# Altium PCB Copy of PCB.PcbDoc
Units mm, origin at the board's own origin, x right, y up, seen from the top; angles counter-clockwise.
Board outline 40 x 38 mm, 2 copper layers (Top Layer, Bottom Layer); 39 components, 67 nets, 273 pads, 70 vias.
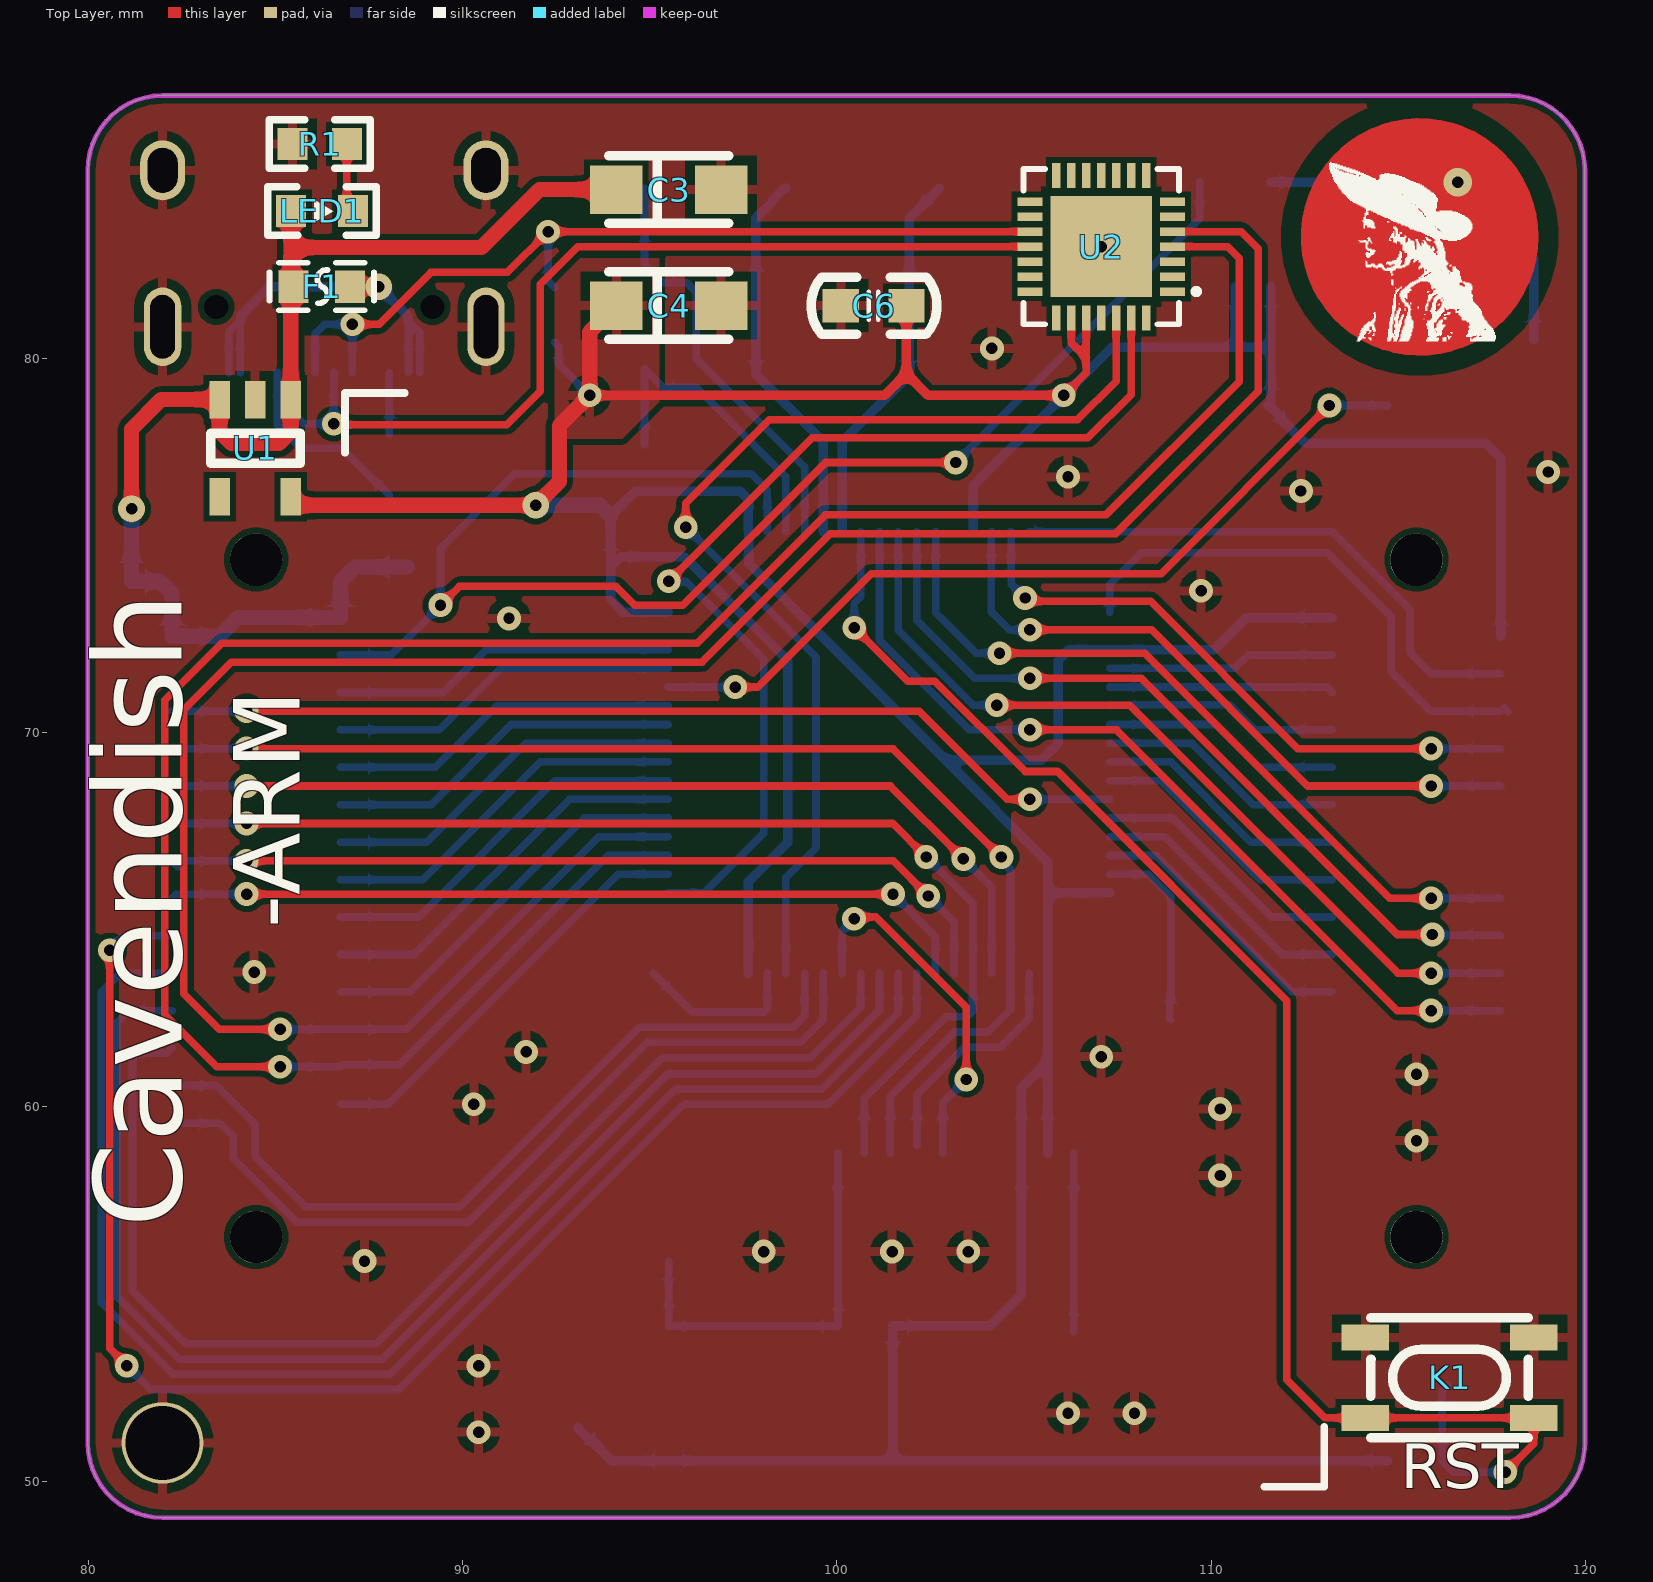
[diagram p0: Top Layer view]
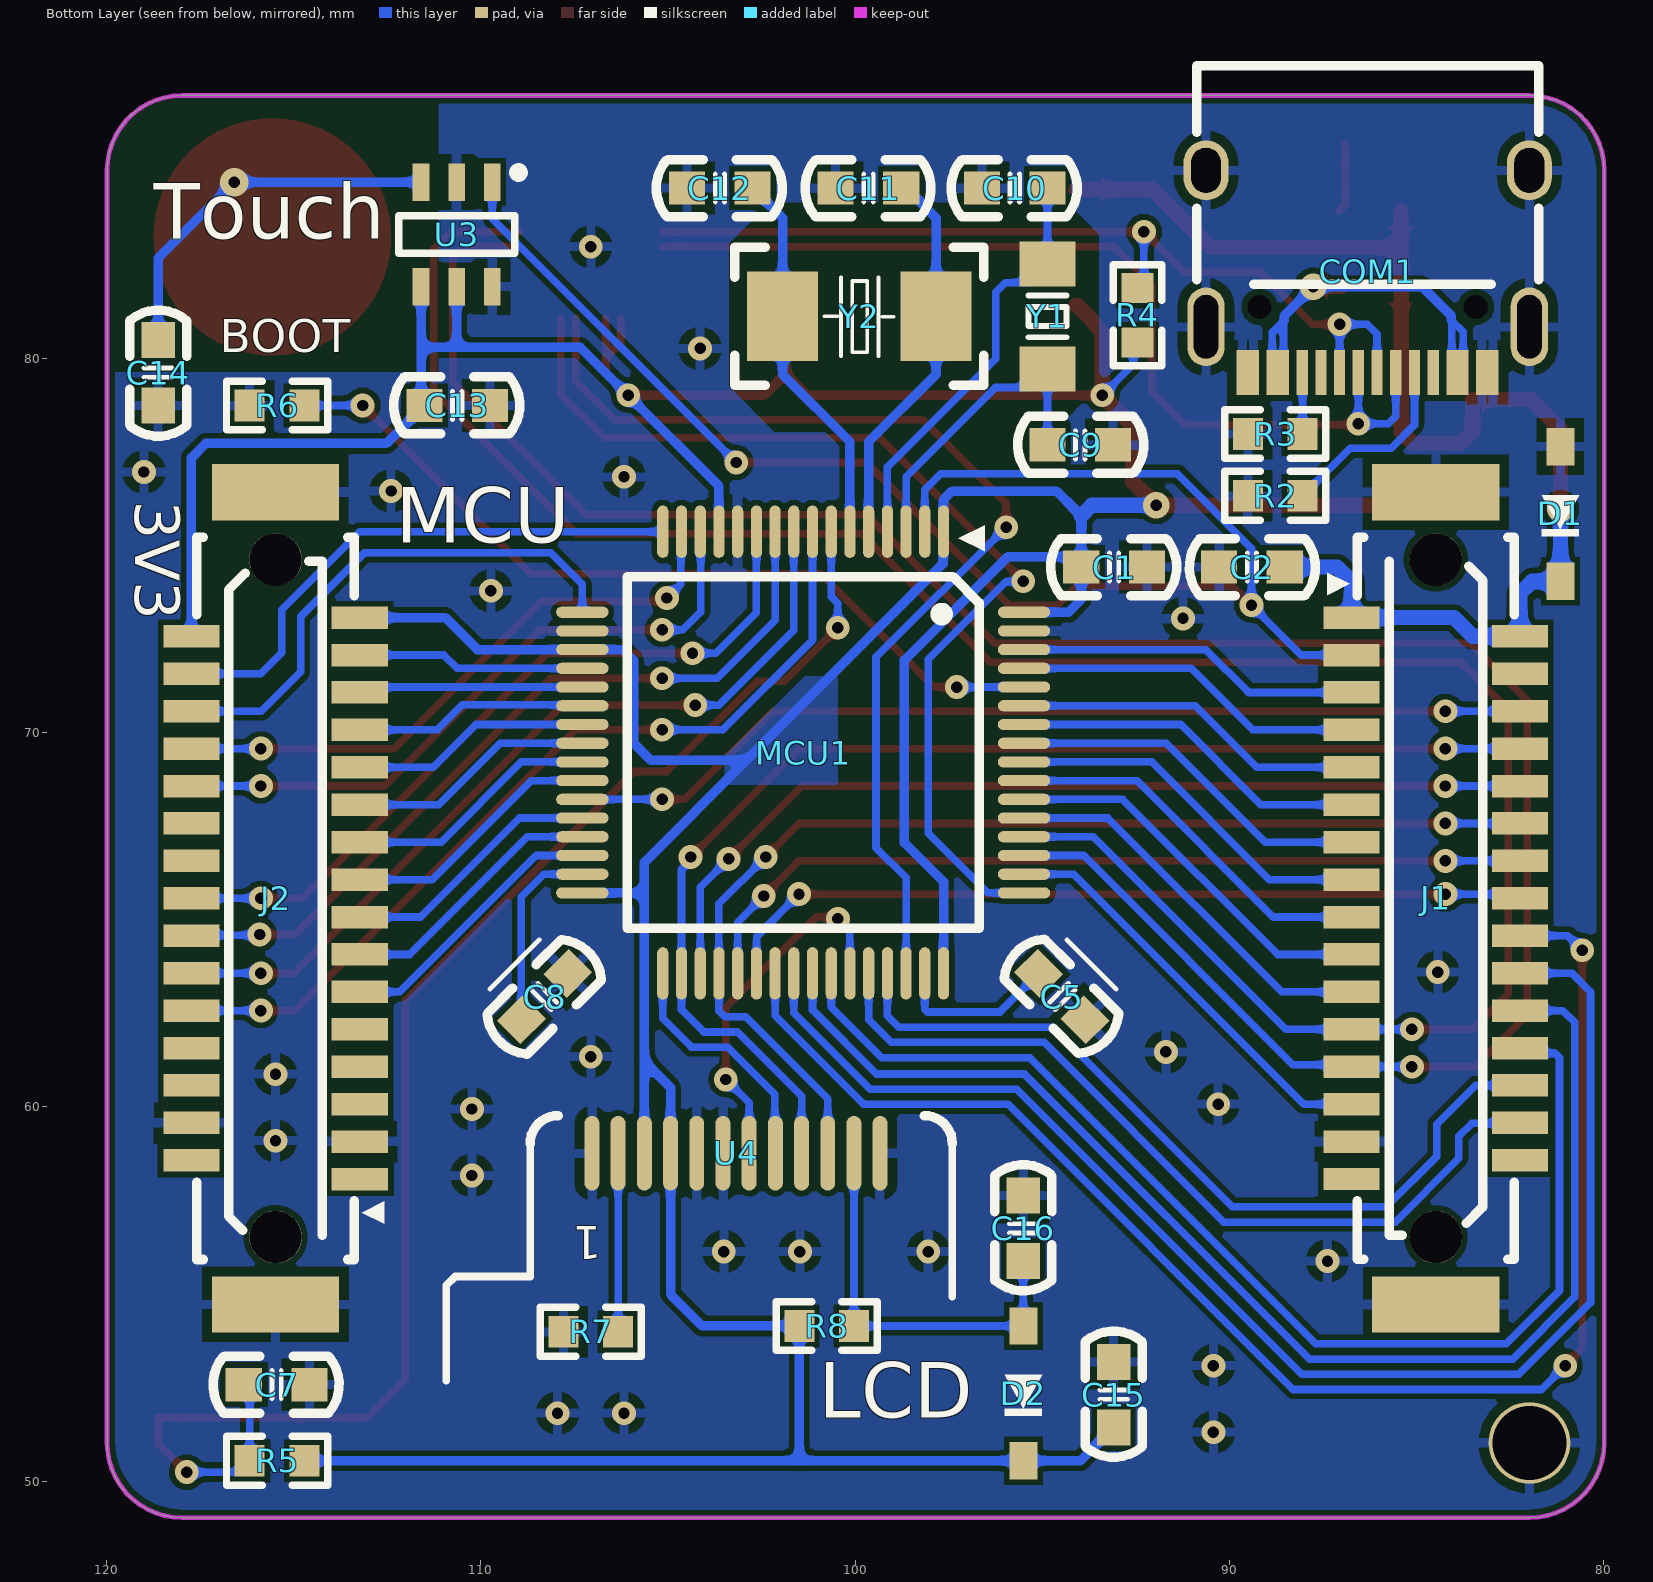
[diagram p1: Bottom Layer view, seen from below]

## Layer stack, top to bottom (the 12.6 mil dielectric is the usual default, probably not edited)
Top Solder: solder mask 0.0102, Solder Resist, Dk 3.5
Top Layer: signal copper 0.0356
Dielectric 1: dielectric 0.32, FR-4, Dk 4.8
Bottom Layer: signal copper 0.0356
Bottom Solder: solder mask 0.0102, Solder Resist, Dk 3.5

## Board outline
79.983,51.022 ccw(c81.983,51.022) 81.983,49.022 117.983,49.022 ccw(c117.983,51.022) 119.983,51.022 119.983,85.022 ccw(c117.983,85.022) 117.983,87.022 82.808,87.022 81.983,87.022 ccw(c81.983,85.022) 79.983,85.022

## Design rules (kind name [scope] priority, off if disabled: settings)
Clearance [All] p1: gap=0.152 ignorepadtopadclearanceinfootprint=TRUE
HoleSize [All] p1: absolutevalues=TRUE maxlimit=10.16 minlimit=0.025 maxpercent=80.000 minpercent=20.000
HoleToHoleClearance [All] p1: gap=0.152 allowstackedmicrovias=TRUE
MinimumSolderMaskSliver [All] p1: minsoldermaskwidth=0.025
PolygonConnect [All] p1: connectstyle=Relief reliefconductorwidth=0.254 reliefentries=4 polygonreliefangle="90 Angle" airgapwidth=0.254
RoutingVias [All] p1: holewidth=0.711 width=1.27 viastyle="Through Hole" minholewidth=0.305 minwidth=0.406 maxholewidth=0.711 maxwidth=1.27
SilkToSilkClearance [All] p1: silktosilkclearance=0
SilkToSolderMaskClearance [IsPad] p1: minsilkscreentomaskgap=0 clearancetoexposedcopper=TRUE
SolderMaskExpansion [All] p1: expansion=0.102 istentingtop=FALSE
Width [All] p1: maxlimit=1.27 minlimit=0.203 preferedwidth=0.254
25 further rules are at their usual default settings.

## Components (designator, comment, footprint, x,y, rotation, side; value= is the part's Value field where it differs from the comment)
C1 "100NF" CAP_0603 92.202,74.422 r0 bottom
C2 "100NF" CAP_0603 90.272,74.422 r180 bottom
C3 "100UF" CAP_3216_A 95.504,84.506 r180 top
C4 "100UF" CAP_3216_A 95.504,81.407 r180 top
C5 "10UF" CAP_0603 93.857,62.327 r45 bottom
C6 "100NF" CAP_0603 100.101,81.407 r0 top
C7 "100NF" CAP_0603 114.579,52.578 r0 bottom
C8 "10UF" CAP_0603 107.676,63.566 r315 bottom
C9 "10PF" CAP_0603 94.859,77.688 r180 bottom
C10 "10PF" CAP_0603 94.859,84.547 r0 bottom
C11 "22PF" CAP_0603 98.765,84.547 r0 bottom
C12 "22PF" CAP_0603 102.737,84.547 r0 bottom
C13 "100NF" CAP_0603 109.753,78.74 r0 bottom
C14 "22PF" CAP_0603 118.618,80.493 r270 bottom
C15 "100NF" CAP_0603 93.091,51.435 r90 bottom
C16 "4.7UF" CAP_0603 95.504,55.88 r90 bottom
COM1 "Type-C" USB-Type-C_16A 86.303,84.997 r0 bottom
D1 "B5819W" DIODE_SOD123 81.153,77.641 r270 bottom
D2 "1N4148" DIODE_SOD123 95.504,54.146 r270 bottom
F1 "FUSE" Fuse_0603 86.233,81.915 r0 top
J1 "31PIN" BTB-DM3-31P 84.483,74.622 r270 bottom
J2 "31PIN" BTB-DM3-31P 115.483,56.522 r90 bottom
K1 "KEY" KEY_SMD 114.118,53.839 r0 top
LED1 "LED_R/G/B/Y" LED_0603_R 86.241,83.932 r180 top
MCU1 "STM32F405RET6" LQFP_64_10X10 101.386,69.466 r0 bottom
R1 "10K" RESC_0603_2 86.182,85.725 r0 top
R2 "5.1K" RESC_0603_2 88.773,76.327 r180 bottom
R3 "5.1K" RESC_0603_2 88.773,77.978 r180 bottom
R4 "5.1K" RESC_0603_2 92.456,81.153 r90 bottom
R5 "10K" RESC_0603_2 115.443,50.546 r0 bottom
R6 "10K" RESC_0603_2 115.443,78.74 r0 bottom
R7 "20R" RESC_0603_2 107.059,53.991 r180 bottom
R8 "4.7K" RESC_0603_2 100.759,54.146 r180 bottom
U1 "SPX3819M5-L" SOT23_5 84.455,77.597 r90 top
U2 "CH549F" QFN28-4X4L 108.969,81.783 r180 top
U3 "TTP223" SOT-23-6 109.692,84.709 r270 bottom
U4 "TFT_1.3_12Pin" LCD_1.3B 107.537,59.26 r180 top
Y1 "32KHz" XTAL_SMD_3215 94.859,81.118 r270 bottom
Y2 "8MHz" XTAL-SMD5032-2P 99.886,81.124 r180 bottom

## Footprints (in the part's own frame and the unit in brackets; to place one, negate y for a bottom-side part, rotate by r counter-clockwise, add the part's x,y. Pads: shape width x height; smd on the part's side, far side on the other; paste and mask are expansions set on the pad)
BTB-DM3-31P [mm]
  rect 0.6x1.5 smd: 1(1.55,-2.25) 2(2.05,2.25) 3(2.55,-2.25) 4(3.05,2.25) 5(3.55,-2.25) 6(4.05,2.25) 7(4.55,-2.25) 8(5.05,2.25) 9(5.55,-2.25) 10(6.05,2.25) 11(6.55,-2.25) 12(7.05,2.25) 13(7.55,-2.25) 14(8.05,2.25) 15(8.55,-2.25) 16(9.05,2.25) 17(9.55,-2.25) 18(10.05,2.25) 19(10.55,-2.25) 20(11.05,2.25) 21(11.55,-2.25) 22(12.05,2.25) 23(12.55,-2.25) 24(13.05,2.25) 25(13.55,-2.25) 26(14.05,2.25) 27(14.55,-2.25) 28(15.05,2.25) 29(15.55,-2.25) 30(16.05,2.25) 31(16.55,-2.25)
  rect 1.5x3.4 smd: 32(19.9,0) 33(-1.8,0)
  round 1.4 hole 1.4 unplated: ""(0,0) ""(18.1,0)
  silkscreen extent -0.6,-2.9 18.7,2.1, body extent -1.51,-2.81 19.59,2.79, height 3.35
CAP_0603 [mil]
  rect 38x35 smd: 1(0,0) 2(69,0)
  silkscreen extent -31,-30 101,30, body extent 4,-16 67,16, height 12
CAP_3216_A [mm]
  rect 1.4x1.3 smd: 1(1.4,0) 2(-1.4,0)
  silkscreen extent -1.6,-0.9 1.6,0.9, body extent -1.6,-0.8 1.6,0.8, height 1.6
DIODE_SOD123 [mm]
  rect 1x0.75 smd: 1(0,0) 2(3.6,0)
  silkscreen extent 1.3,-0.5 2.4,0.5, body extent -0.05,-0.8 3.65,0.8, height 1.27
Fuse_0603 [mil]
  rect 31.8x34 smd mask+2: 1(-29.7,0) 2(29.7,0)
  silkscreen extent -55,-25 55,25, body extent -33,-18 34,18, height 30
KEY_SMD [mm] "3*4*2.5MM"
  rect 1.27x0.7 smd: 1(0,0) 1(4.5,0) 2(0,-2.15) 2(4.5,-2.15)
  silkscreen extent 0.15,-2.68 4.35,0.52, body extent -0.1,-2.67 4.6,0.53, height 2.51
LCD_1.3B [mm]
  oval 0.4x2 smd far side: 1(0.508,0.5) 2(1.208,0.5) 3(1.908,0.5) 4(2.608,0.5) 5(3.308,0.5) 6(4.008,0.5) 7(4.708,0.5) 8(5.408,0.5) 9(6.108,0.5) 10(6.808,0.5) 11(7.508,0.5) 12(8.208,0.5)
  silkscreen extent -5.48,-19.81 20.68,9.41, body extent -5.48,-19.81 20.68,9.41, height 1
LED_0603_R [mm]
  rect 0.8x0.85 smd: 1(-0.832,0) 2(0.832,0)
  silkscreen extent -1.45,-0.65 1.45,0.65, body extent -0.81,-0.4 0.81,0.4, height 0.6
LQFP_64_10X10 [mm]
  oval 0.3x1.4 smd: 1(-3.75,-5.9) 2(-3.25,-5.9) 3(-2.75,-5.9) 4(-2.25,-5.9) 5(-1.75,-5.9) 6(-1.25,-5.9) 7(-0.75,-5.9) 8(-0.25,-5.9) 9(0.25,-5.9) 10(0.75,-5.9) 11(1.25,-5.9) 12(1.75,-5.9) 13(2.25,-5.9) 14(2.75,-5.9) 15(3.25,-5.9) 16(3.75,-5.9) 33(3.75,5.9) 34(3.25,5.9) 35(2.75,5.9) 36(2.25,5.9) 37(1.75,5.9) 38(1.25,5.9) 39(0.75,5.9) 40(0.25,5.9) 41(-0.25,5.9) 42(-0.75,5.9) 43(-1.25,5.9) 44(-1.75,5.9) 45(-2.25,5.9) 46(-2.75,5.9) 47(-3.25,5.9) 48(-3.75,5.9)
  oval 1.4x0.3 smd: 17(5.9,-3.75) 18(5.9,-3.25) 19(5.9,-2.75) 20(5.9,-2.25) 21(5.9,-1.75) 22(5.9,-1.25) 23(5.9,-0.75) 24(5.9,-0.25) 25(5.9,0.25) 26(5.9,0.75) 27(5.9,1.25) 28(5.9,1.75) 29(5.9,2.25) 30(5.9,2.75) 31(5.9,3.25) 32(5.9,3.75) 49(-5.9,3.75) 50(-5.9,3.25) 51(-5.9,2.75) 52(-5.9,2.25) 53(-5.9,1.75) 54(-5.9,1.25) 55(-5.9,0.75) 56(-5.9,0.25) 57(-5.9,-0.25) 58(-5.9,-0.75) 59(-5.9,-1.25) 60(-5.9,-1.75) 61(-5.9,-2.25) 62(-5.9,-2.75) 63(-5.9,-3.25) 64(-5.9,-3.75)
  silkscreen extent -4.85,-6.08 4.7,4.7, body extent -6.07,-6.07 6.07,6.07, height 1.62
QFN28-4X4L [mil]
  rect 26.2x8.8 smd mask+2: 1(0,0) 2(0,-15.7) 3(0,-31.5) 4(0,-47.2) 5(0,-63) 6(0,-78.7) 7(0,-94.4) 15(150.2,-94.4) 16(150.2,-78.7) 17(150.2,-63) 18(150.2,-47.2) 19(150.2,-31.5) 20(150.2,-15.7) 21(150.2,0)
  rect 8.8x26.2 smd mask+2: 8(27.9,-122.3) 9(43.6,-122.3) 10(59.4,-122.3) 11(75.1,-122.3) 12(90.9,-122.3) 13(106.6,-122.3) 14(122.3,-122.3) 22(122.3,27.9) 23(106.6,27.9) 24(90.9,27.9) 25(75.1,27.9) 26(59.4,27.9) 27(43.6,27.9) 28(27.9,27.9)
  rect 106.3x106.3 smd mask+2: 29(75.1,-47.2)
  silkscreen extent -28,-129 157,35, body extent -4,-126 154,32, height 35
RESC_0603_2 [mm]
  rect 0.8x0.85 smd: 1(-0.73,0) 2(0.73,0)
  silkscreen extent -1.35,-0.65 1.35,0.65, body extent -0.8,-0.4 0.8,0.4, height 0.38
SOT23_5 [mm]
  rect 1x0.55 smd: 1(1.3,-0.95) 2(1.3,0) 3(1.3,0.95) 4(-1.3,0.95) 5(-1.3,-0.95)
  silkscreen extent -0.4,-1.21 0.4,1.19, body extent -1.52,-1.51 1.48,1.49, height 1.3
SOT-23-6 [mm]
  rect 1x0.45 smd: 1(0,0) 2(0,-0.95) 3(0,-1.9) 4(2.794,-1.9) 5(2.794,-0.95) 6(2.794,0)
  silkscreen extent -0.38,-2.5 1.91,0.82, body extent -0.01,-2.45 2.8,0.55, height 1.15
USB-Type-C_16A [mm]
  round 0 hole 0.65: 0(-2.89,3.625) 0(2.89,3.625)
  oval 1.2x1.6 hole 0.8 slot 1.2 at 90 deg: 1(-4.32,-0.025) 1(4.32,-0.025)
  oval 1x2.1 hole 0.66 slot 1.7 at 90 deg: 1(-4.32,4.155) 1(4.32,4.155)
  rect 0.3x1.2 smd: A1(-3.35,5.375) A4(-2.55,5.375) A5(-1.25,5.375) A6(-0.25,5.375) A7(0.25,5.375) A8(-1.75,5.375) A9(2.55,5.375) A12(3.35,5.375) B1(3.05,5.375) B4(2.25,5.375) B5(1.75,5.375) B6(0.75,5.375) B7(-0.75,5.375) B8(1.25,5.375) B9(-2.25,5.375) B12(-3.05,5.375)
  silkscreen extent -4.57,-2.82 4.57,3.02, body extent -4.47,-2.63 4.47,5.27, height 3.25
XTAL-SMD5032-2P [mil]
  rect 74.8x94.5 smd mask+2: 1(-80.7,0) 2(80.7,0)
  silkscreen extent -131,-73 131,73, body extent -98,-63 99,63, height 39
XTAL_SMD_3215 [mm]
  rect 1.2x1.5 smd: 1(-1.4,0) 2(1.4,0)
  silkscreen extent -0.56,-0.51 0.56,0.51, body extent -1.61,-0.76 1.61,0.76, height 0.91

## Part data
C1 C2 C5 C6 C7 C8 C9 C10 C11 C12 C13 C14 C15 C16: library part CAP, "CAP  12~50V"
C3 C4: library part CAP_TA, "CAP  6~12V  钽电容"
COM1: library part USB-type_c, "USB"
D1 D2: library part Diode-SM, "Diode_肖特基/二极管"
J1 J2: library part BTB_DF3_31Pin, "BTB"
K1: "Key"
LED1: library part LED_SMT, "LED"
MCU1: library part STM32f4_R, "MCU"
R1 R5 R6 R7 R8: library part RES_S, "RES 贴片"
R2 R3 R4: library part RES, "RES 贴片"
U1: "DC-DC   3.3V  500ma"
U2: "MCU", External Clock Frequency Rang=6MHz~25MHz, JLCPCB Part Class="Extended Part", Manufacturer=WCH(南京沁恒), Maximum Frequency=48MHz, Operating Temperature Range=-40~+70, Supply Voltage Range=3.3V~5V
U3: "触摸芯片"
U4: library part "LCD_1.3   T", "ST7789V-SPI"
Y1 Y2: library part XTAL, "CRYSTAL"

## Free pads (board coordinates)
  round 2.184 hole 1.981: 0(81.983,51.022)

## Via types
v1: diameter 0.635, hole 0.305, Top Layer to Bottom Layer, tented both sides, 66 vias
v2: diameter 0.711, hole 0.305, Top Layer to Bottom Layer, tented both sides, 3 vias
v3: diameter 0.762, hole 0.305, Top Layer to Bottom Layer, tented both sides, 1 vias

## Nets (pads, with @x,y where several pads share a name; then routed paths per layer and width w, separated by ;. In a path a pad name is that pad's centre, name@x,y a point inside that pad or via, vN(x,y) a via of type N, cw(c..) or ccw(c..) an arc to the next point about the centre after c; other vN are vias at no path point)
+5: C2.2 C3.1 D1.2 F1.1 J1.1 J1.2 LED1.2 U1.1 U1.3 | length 35.2
  Top Layer w0.406: v2@81.153,75.819 v2(81.153,75.977) 81.153,78.105 81.945,78.897 U1.3 83.505,78.039 83.82,77.724 85.09,77.724 85.405,78.039 U1.1 F1.1@85.405,81.915 ; LED1.2 85.409,82.958 ; F1.1 85.409,81.984 85.409,82.958 ; C3.1 92.05,84.506 90.502,82.958 85.409,82.958
  Bottom Layer w0.406: v2(81.153,75.977) D1.2 81.915,74.041 82.233,73.723 J1.2 83.494,72.572 83.994,73.072 J1.1 86.733,74.033 87.122,74.422 C2.2
BOOT0: MCU1.60 R6.1 | length 22.3
  Top Layer w0.203: v1(97.282,71.216) 97.886,71.216 100.914,74.244 108.661,74.244 v1(113.157,78.74)
  Bottom Layer w0.203: MCU1.60 v1(97.282,71.216) ; v1(113.157,78.74) R6.1
BOOT1: J2.15 MCU1.28 | length 7
  Bottom Layer w0.203: MCU1.28 108.966,67.716 111.611,65.072 J2.15
CAN_RX: J1.28 MCU1.44 | length 22.3
  Bottom Layer w0.203: J1.28 82.242,59.563 83.515,59.563 83.866,59.212 83.866,58.628 85.573,56.921 90.145,56.921 94.945,61.722 99.035,61.722 99.636,62.324 MCU1.44
CAN_TX: J1.26 MCU1.45 | length 22
  Bottom Layer w0.203: J1.26 83.42,60.572 84.455,59.538 84.455,58.674 85.801,57.328 89.917,57.328 94.718,62.128 98.827,62.128 99.136,62.438 MCU1.45
CC1: COM1.A5 R2.2 | length 5.2
  Bottom Layer w0.203: COM1.A5 85.053,78.218 85.674,77.597 86.773,77.597 87.72,76.65 87.745,76.65 88.043,76.352 R2.2
CC2: COM1.B5 R3.2 | length 1.6
  Bottom Layer w0.203: R3.2 COM1.B5@88.043,79.612
CH_RXD: J1.25 MCU1.51 U2.4 | length 62.2
  Top Layer w0.203: v1(85.121,61.072) 83.428,61.072 82.042,62.459 82.042,64.516 82.042,70.866 83.566,72.39 96.266,72.39 99.695,75.819 107.188,75.819 110.744,79.375 110.744,82.677 110.439,82.982 U2.4
  Bottom Layer w0.203: v1(85.121,61.072) J1.25 86.787,61.126 88.304,61.126 93.894,66.716 MCU1.51
CH_TXD: J1.23 MCU1.52 U2.5 | length 61.6
  Top Layer w0.203: v1(85.121,62.072) 83.495,62.072 82.55,63.017 82.55,70.612 83.82,71.882 96.393,71.882 99.822,75.311 107.442,75.311 111.252,79.121 111.252,82.931 110.8,83.383 U2.5
  Bottom Layer w0.203: v1@85.115,62.078 v1(85.121,62.072) J1.23 88.488,62.072 93.632,67.216 MCU1.52
D+: COM1.A6 COM1.B6 R4.2 U2.17 | length 24.1
  Top Layer w0.203: v1(87.053,80.907) 87.765,80.907 89.154,82.296 91.194,82.296 v1(92.281,83.383) U2.17
  Bottom Layer w0.203: COM1.A6 86.053,80.643 86.317,80.907 v1(87.053,80.907) COM1.B6 ; v1(92.281,83.383) 92.281,82.058 R4.2
D-: COM1.A7 COM1.B7 U2.18 | length 25.9
  Top Layer w0.203: v1@86.583,78.224 91.178,78.224 92.075,79.121 92.075,81.984 93.073,82.982 U2.18
  Bottom Layer w0.203: COM1.B7 85.553,78.455 85.754,78.254 v1(86.553,78.254) COM1.A7 COM1.A7@86.583,79.592
D/C: MCU1.43 U4.7 | length 9.8
  Top Layer w0.203: v1(100.457,65.024) 100.508,65.075 101.041,65.075 103.454,62.662 v1(103.454,60.731)
  Bottom Layer w0.203: MCU1.43 100.136,64.689 100.457,65.01 v1(100.457,65.024) ; U4.7 102.829,60.106 v1(103.454,60.731)
DAC_OUT1: J2.29 MCU1.20 | length 6.1
  Bottom Layer w0.203: MCU1.20 110.629,71.716 110.985,72.072 J2.29
DAC_OUT2: J2.27 MCU1.21 | length 6
  Bottom Layer w0.203: MCU1.21 113.088,71.216 J2.27
DIR: J2.21 MCU1.24 | length 6.6
  Bottom Layer w0.203: MCU1.24 109.481,69.716 111.125,68.072 J2.21
GND: C1.1 C2.1 C3.2 C4.2 C5.1 C6.1 C7.1 C8.1 C9.2 C10.2 C11.2 C12.2 C13.1 C14.2 C15.2 C16.2 COM1.1 COM1.A1 COM1.A12 COM1.B1 COM1.B12 D1.1 J1.29 J1.32 J1.33 J2.3 J2.4 J2.32 J2.33 K1.1 MCU1.12 MCU1.18 MCU1.63 pad.0 R1.1 R2.1 R3.1 R6.2 R7.1 U1.2 U2.29 U3.2 U3.6 U4.1 U4.5 U4.6 U4.12
  other v1: 90.424,51.308 106.172,51.816 107.95,51.816 90.424,53.086 87.376,55.88 98.044,56.134 101.473,56.134 103.505,56.134 110.236,58.166 115.483,59.095 110.236,59.944 90.297,60.071 115.483,60.873 107.061,61.341 91.694,61.468 84.43,63.602 91.237,73.05 109.728,73.787 112.395,76.454 106.172,76.835 118.999,76.962 104.14,80.264 107.061,82.982
GPIOA: J1.15 MCU1.56 | length 10.1
  Bottom Layer w0.203: J1.15 88.932,66.072 92.076,69.216 MCU1.56
GPIOB: J1.13 MCU1.57 | length 9.8
  Bottom Layer w0.203: J1.13 89.043,67.072 91.687,69.716 MCU1.57
MISO_2: J1.10 MCU1.35 | length 25.3
  Top Layer w0.203: v1(84.226,68.572) 101.43,68.572 v1(103.378,66.624)
  Bottom Layer w0.203: J1.10 v1(84.226,68.572) ; v1(103.378,66.624) 104.136,65.866 MCU1.35
MOSI_2: J1.12 MCU1.36 U4.10 | length 30.5
  Top Layer w0.203: v1(84.226,67.572) 101.49,67.572 v1(102.387,66.675)
  Bottom Layer w0.203: J1.12 v1(84.226,67.572) ; U4.10 100.729,60.216 102.921,62.408 103.48,62.408 103.636,62.564 MCU1.36 103.636,65.426 v1(102.387,66.675)
NetC5_2: C5.2 MCU1.47 | length 4.5
  Bottom Layer w0.203: C5.2 96.128,62.535 98.063,62.535 98.136,62.608 MCU1.47
NetC8_2: C8.2 MCU1.31 | length 5.2
  Bottom Layer w0.203: MCU1.31 108.312,66.216 108.916,65.613 108.916,62.866 108.889,62.839 108.889,62.354 C8.2
NetLED1_1: LED1.1 R1.2 | length 1.9
  Top Layer w0.203: R1.2@86.904,85.717 86.904,84.1 LED1.1
NetR7_2: R7.2 U4.2 | length 4.8
  Bottom Layer w0.203: R7.2 U4.2
NRST: C7.2 K1.2 MCU1.7 R5.2 | length 41.2
  Top Layer w0.203: v1(100.461,72.8) 101.887,71.374 102.616,71.374 105.029,68.961 105.893,68.961 112.014,62.84 112.014,52.705 113.03,51.689 114.118,51.689 118.618,51.689 118.618,51.003 v1(117.856,50.241)
  Bottom Layer w0.203: v1(100.461,72.8) 100.461,73.461 100.636,73.636 MCU1.7 ; C7.2 116.173,52.419 116.173,50.54 116.471,50.241 v1(117.856,50.241)
NSS_2: MCU1.33 U4.8 | length 6.4
  Bottom Layer w0.203: U4.8@102.129,58.963 102.144,58.978 102.144,60.335 103.403,61.595 104.369,61.595 105.136,62.363 MCU1.33
NSS_2_2: J1.6 MCU1.27 | length 26
  Top Layer w0.203: v1(84.226,70.572) 102.199,70.572 104.554,68.216 v1(105.156,68.216)
  Bottom Layer w0.203: J1.6 v1(84.226,70.572) ; v1(105.156,68.216) MCU1.27
NSS_2_3: J2.17 MCU1.26 | length 7
  Bottom Layer w0.203: MCU1.26 108.652,68.716 111.296,66.072 J2.17
PC00: J2.10 MCU1.8 | length 23.6
  Top Layer w0.203: v1(105.156,70.079) 107.467,70.079 114.974,62.572 v1(115.875,62.572)
  Bottom Layer w0.203: MCU1.8 101.136,72.473 103.53,70.079 v1(105.156,70.079) ; v1(115.875,62.572) J2.10
PC01: J2.12 MCU1.9 | length 22.5
  Top Layer w0.203: v1(104.271,70.735) 107.827,70.735 114.99,63.572 v1(115.875,63.572)
  Bottom Layer w0.203: MCU1.9 101.636,72.735 103.636,70.735 v1(104.271,70.735) ; v1(115.875,63.572) J2.12
PC02: J2.14 MCU1.10 | length 21.5
  Top Layer w0.203: v1(105.156,71.45) 108.128,71.45 114.973,64.605 v1(115.908,64.605)
  Bottom Layer w0.203: MCU1.10 102.136,72.997 103.683,71.45 v1(105.156,71.45) ; v1(115.908,64.605) 115.925,64.589 117.716,64.589 J2.14
PC03: J2.16 MCU1.11 | length 20.4
  Top Layer w0.203: v1(104.343,72.122) 108.218,72.122 114.768,65.572 v1(115.875,65.572)
  Bottom Layer w0.203: MCU1.11 102.636,73.208 103.722,72.122 v1(104.343,72.122) ; v1(115.875,65.572) J2.16
PC12: J1.21 MCU1.53 | length 10.7
  Bottom Layer w0.203: J1.21 88.599,63.072 93.243,67.716 MCU1.53
PC13: J1.3 MCU1.2 U3.1 | length 41.6
  Top Layer w0.203: v1(89.408,73.406) 89.916,73.914 94.092,73.914 94.6,73.406 95.885,73.406 99.695,77.216 v1(103.175,77.216)
  Bottom Layer w0.203: J1.3 88.074,72.072 v1(89.408,73.406) 89.408,74.93 91.391,76.913 97.712,76.913 98.136,76.489 MCU1.2 ; v1(103.175,77.216) 109.692,83.734 U3.1
PD02: J1.19 MCU1.54 | length 10.5
  Bottom Layer w0.203: J1.19 88.71,64.072 92.854,68.216 MCU1.54
RES: C16.1 D2.1 R8.2 U4.11 | length 10.9
  Bottom Layer w0.203: C16.1 D2.1 R8.2 U4.11
SCK_2: J1.8 MCU1.34 U4.9 | length 33.2
  Top Layer w0.203: v1(84.226,69.572) 101.497,69.572 v1(104.394,66.675)
  Bottom Layer w0.203: J1.8 v1(84.226,69.572) ; U4.9 101.429,60.281 103.149,62.001 104.038,62.001 104.636,62.599 MCU1.34 104.636,66.34 104.394,66.582 v1(104.394,66.675)
SCL_2: J2.13 MCU1.29 | length 7.2
  Bottom Layer w0.203: MCU1.29 108.755,67.216 111.899,64.072 J2.13
SDA_2: J2.11 MCU1.30 | length 7.5
  Bottom Layer w0.203: MCU1.30 108.518,66.716 112.163,63.072 J2.11
STEP: J2.19 MCU1.25 | length 6.8
  Bottom Layer w0.203: MCU1.25 108.914,69.216 111.058,67.072 J2.19
SWCLK: MCU1.49 U2.27 | length 27.7
  Top Layer w0.203: v1(95.504,74.041) 99.339,77.876 106.705,77.876 107.861,79.032 U2.27
  Bottom Layer w0.203: MCU1.49 96.45,65.716 98.044,67.31 98.044,71.956 95.968,74.032 95.513,74.032 v1(95.504,74.041)
SWDIO: MCU1.46 U2.26 | length 28.9
  Top Layer w0.203: v1(95.961,75.489) 95.961,76.124 98.196,78.359 106.426,78.359 107.46,79.393 U2.26
  Bottom Layer w0.203: v1(95.961,75.489) 99.441,72.009 99.441,66.929 98.636,66.124 MCU1.46
TM1_CH1: J1.22 MCU1.41 | length 34.8
  Bottom Layer w0.203: J1.22 81.089,62.572 80.772,62.255 80.772,54.921 82.432,53.261 87.856,53.261 95.472,60.877 99.425,60.877 101.136,62.589 MCU1.41
TM1_CH2: J1.24 MCU1.42 | length 32.1
  Bottom Layer w0.203: J1.24 82.094,61.433 81.297,61.433 81.178,61.314 81.178,55.09 82.601,53.667 87.687,53.667 95.336,61.316 99.289,61.316 100.636,62.663 MCU1.42
TM2_CH1: J1.27 MCU1.50 | length 11.3
  Bottom Layer w0.203: J1.27 88.012,60.072 94.156,66.216 MCU1.50
TM2_CH2: J1.17 MCU1.55 | length 10.3
  Bottom Layer w0.203: J1.17 88.821,65.072 92.465,68.716 MCU1.55
TM3_CH1: J2.25 MCU1.22 | length 6.2
  Bottom Layer w0.203: MCU1.22 107.292,70.716 107.315,70.739 107.319,70.735 107.923,70.735 107.927,70.739 110.49,70.739 111.157,70.072 J2.25
TM3_CH2: J2.23 MCU1.23 | length 6.4
  Bottom Layer w0.203: MCU1.23 110.124,70.216 111.268,69.072 J2.23
TM4_CH1: J1.11 MCU1.58 | length 9.6
  Bottom Layer w0.203: J1.11 89.154,68.072 91.298,70.216 MCU1.58
TM4_CH2: J1.9 MCU1.59 | length 9.4
  Bottom Layer w0.203: J1.9 89.265,69.072 90.909,70.716 MCU1.59
TM4_CH3: J1.7 MCU1.61 | length 9.4
  Bottom Layer w0.203: J1.7 89.376,70.072 91.02,71.716 MCU1.61
TM4_CH4: J1.5 MCU1.62 | length 9.2
  Bottom Layer w0.203: J1.5 89.487,71.072 90.631,72.216 MCU1.62
TM5_CH1: J2.22 MCU1.14 | length 17.7
  Top Layer w0.203: v1(105.156,72.745) 108.408,72.745 112.581,68.572 v1(115.875,68.572)
  Bottom Layer w0.203: MCU1.14 104.12,75.35 104.12,73.223 104.598,72.745 v1(105.156,72.745) ; v1(115.875,68.572) J2.22
TM5_CH2: J2.24 MCU1.15 | length 16.2
  Top Layer w0.203: v1@105.154,73.469 105.19,73.505 108.384,73.505 112.317,69.572 v1(115.875,69.572)
  Bottom Layer w0.203: MCU1.15 104.655,75.348 104.655,73.968 v1(105.027,73.596) ; v1(115.875,69.572) J2.24
TM8_CH1: J1.14 MCU1.37 | length 23.2
  Top Layer w0.203: v1(84.226,66.572) 101.5,66.572 v1(102.438,65.634)
  Bottom Layer w0.203: J1.14@82.384,66.421 J1.14 v1(84.226,66.572) ; v1(102.438,65.634) 103.136,64.936 MCU1.37
TM8_CH2: J1.16 MCU1.38 | length 21.9
  Top Layer w0.203: v1(84.226,65.684) v1(101.498,65.684)
  Bottom Layer w0.203: J1.16 82.345,65.684 v1(84.226,65.684) ; v1(101.498,65.684) 102.631,64.551 102.631,63.571 MCU1.38
TM8_CH3: J1.18 MCU1.39 | length 39.8
  Top Layer w0.203: v1(80.569,64.186) 80.569,53.548 81.026,53.091 v1(81.026,53.086)
  Bottom Layer w0.203: v1(80.569,64.186) 80.955,64.572 J1.18 ; v1(81.026,53.086) 81.664,52.448 88.288,52.448 95.904,60.065 99.762,60.065 102.136,62.439 MCU1.39
TM8_CH4: J1.20 MCU1.40 | length 37.5
  Bottom Layer w0.203: J1.20 80.844,63.572 80.351,63.079 80.351,54.767 82.264,52.855 88.059,52.855 95.675,60.471 99.593,60.471 101.636,62.514 MCU1.40
Touch: C14.1 U3.3 | length 29.2
  Top Layer w0.254: 118.618,83.244 ccw(c115.57,83.244) 118.618,83.244
  Bottom Layer w0.254: U3.3 v3(116.586,84.709) 118.618,82.677 C14.1
UART-RXD2: J2.26 MCU1.17 | length 14.3
  Bottom Layer w0.203: MCU1.17 107.286,73.961 108.128,74.803 113.106,74.803 114.808,73.101 114.808,71.628 115.864,70.572 J2.26 ; J2.26@117.831,70.67 J2.26@117.939,70.561
UART-TXD2: J2.28 MCU1.16 | length 14.8
  Bottom Layer w0.203: MCU1.16 113.229,75.366 115.316,73.279 115.316,72.136 115.88,71.572 J2.28
VBUS: COM1.A4 COM1.A9 COM1.B4 COM1.B9 F1.2 | length 11.9
  Top Layer w0.406: F1.2 v2(87.757,81.915)
  Bottom Layer w0.203: COM1.A4 83.753,80.705 84.053,81.005 COM1.B9 ; COM1.B4 88.553,80.992 88.853,80.692 COM1.A9
  Bottom Layer w0.254: 84.068,81.02 84.068,81.134 84.849,81.915 v2(87.757,81.915) 88.538,81.134 88.538,81.007 88.553,80.992
VDD: C1.2 C4.1 C6.2 C13.2 C15.1 D2.2 J2.30 J2.31 MCU1.1 MCU1.13 MCU1.19 MCU1.32 MCU1.48 MCU1.64 R4.1 R5.1 R8.1 U1.5 U2.23 U2.24 U3.4 U3.5 U4.3 U4.4 | length 156.9
  Top Layer w0.203: v1(106.061,79.01) 106.66,79.609 106.66,80.01 ; U2.23 106.261,80.409 106.66,80.01 ; U2.24 106.66,80.01
  Top Layer w0.254: v1(93.393,79.01) 101.273,79.01 101.854,79.591 ; C6.2 101.854,79.591 ; v1(106.061,79.01) 102.435,79.01 101.854,79.591
  Top Layer w0.406: U1.5 85.405,76.094 85.426,76.073 v2(91.948,76.073) 92.583,76.708 92.583,78.2 v1(93.393,79.01) 93.393,80.706 93.607,80.921 93.607,80.96 94.054,81.407 C4.1
  Bottom Layer w0.203: R4.1 92.566,80.313 92.566,79.837 v1(93.393,79.01)
  Bottom Layer w0.254: C15.1 93.091,51.397 93.408,51.079 93.447,51.079 93.98,50.546 101.489,50.546 ; MCU1.64 94.297,73.216 93.955,73.558 C1.2 ; MCU1.48 97.636,66.013 98.679,67.056 98.679,71.932 95.91,74.701 94.234,74.701 C1.2 ; MCU1.13 103.636,76.585 v1(106.061,79.01) 107.34,80.289 110.642,80.289 ; U4.3 105.629,61.214 ; MCU1.32 105.629,65.716 ; U3.5 110.642,80.289 ; U3.4 111.592,80.289 ; J2.31 110.943,73.072 110.088,72.216 MCU1.19 106.202,72.216 105.918,71.933 105.918,69.723 105.461,69.266 102.895,69.266 ; R5.1 101.489,50.546 ; J2.30 117.733,77.339 117.348,77.724 112.522,77.724 111.862,78.384 111.862,78.422 111.544,78.74 C13.2 111.592,78.826 111.592,80.289 ; C1.2 93.955,75.794 94.615,76.454 97.409,76.454 97.636,76.227 MCU1.1 97.645,75.358 97.645,74.516 102.895,69.266 ; 101.489,50.546 R8.1 104.084,54.146 104.929,54.991 U4.4 104.929,60.514 105.629,61.214 ; 102.895,69.266 105.629,66.532 105.629,65.716 ; 105.629,61.214 105.629,65.716 ; 110.642,80.289 111.592,80.289
  Bottom Layer w0.406: v2(91.948,76.073) 93.675,76.073 93.955,75.794
XTALA: C11.1 MCU1.5 Y2.2 | length 10.3
  Bottom Layer w0.254: C11.1@98.638,84.547 98.6,84.547 98.257,84.204 98.257,84.166 97.836,83.746 Y2.2 97.836,79.569 99.636,77.77 MCU1.5
XTALB: C12.1 MCU1.6 Y2.1 | length 10.3
  Bottom Layer w0.254: MCU1.6 100.136,77.77 101.936,79.569 Y2.1 101.936,83.746 C12.1
XTALC: C9.1 MCU1.3 Y1.2 | length 8.5
  Bottom Layer w0.203: C9.1 Y1.2 95.358,79.219 96.25,79.219 98.636,76.833 MCU1.3
XTALD: C10.1 MCU1.4 Y1.1 | length 13
  Bottom Layer w0.203: C10.1@94.859,84.176 Y1.1 ; C10.1 Y1.1 ; MCU1.4 99.136,77.095 96.241,79.99 96.241,81.768 95.99,82.019 95.358,82.019 Y1.1
pads on no net: COM1.0 COM1.A8 COM1.B8 J1. J1.4 J1.30 J1.31 J2. J2.1 J2.2 J2.5 J2.6 J2.7 J2.8 J2.9 J2.18 J2.20 U1.4 U2.1 U2.2 U2.3 U2.6 U2.7 U2.8 U2.9 U2.10 U2.11 U2.12 U2.13 U2.14 U2.15 U2.16 U2.19 U2.20 U2.21 U2.22 U2.25 U2.28

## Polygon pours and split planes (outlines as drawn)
GND on Bottom Layer "GND_L02_P003" (solid, remove dead copper, pour order 3): 78.44,89.949 125.94,89.949 125.94,47.449 78.44,47.449
VDD on Bottom Layer "VDD_L02_P000" (solid, remove dead copper, pour order 0): 100.457,71.501 100.457,68.605 103.48,68.605 103.48,69.367 101.346,71.501
VDD on Top Layer "VDD_L01_P001" (solid, remove dead copper, pour order 1): 92.456,82.677 95.25,82.677 95.25,78.842 94.259,77.851 92.71,77.851 92.456,78.105
GND on Top Layer "GND_L01_P004" (solid, remove dead copper, pour order 4): 77.5,90 125,90 125,47.5 77.5,47.5

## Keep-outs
Keep-Out Layer:
  the board outline again, w0.127

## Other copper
Top Layer:
  pour cut-out: 111.862,83.244 ccw(c115.57,83.244) 115.57,79.536 ccw(c115.57,83.244) 119.278,83.244 ccw(c115.57,83.244) 115.57,86.952 ccw(c115.57,83.244)
  region net Touch: 112.522,83.244 ccw(c115.57,83.244) 115.57,80.196 ccw(c115.57,83.244) 118.618,83.244 ccw(c115.57,83.244) 115.57,86.292 ccw(c115.57,83.244)
  pour cut-out: 85.598,81.661 86.614,81.661 86.614,80.614 86.612,80.612 85.631,80.612 85.598,80.645
  pour cut-out: 102.235,69.596 103.759,69.596 104.648,68.707 104.648,66.548 102.514,66.548 102.387,66.675
Bottom Layer:
  pour cut-out: 111.125,87 120.5,87 120.5,79.629 111.125,79.629
  pour cut-out: 93.472,83.312 94.326,84.166 102.27,84.166 103.378,83.058 103.378,79.248 102.159,78.029 94.691,78.029 93.472,79.248

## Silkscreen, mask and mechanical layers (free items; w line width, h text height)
Top Overlay:
  drawing of 789 lines, arcs and shapes, not listed
  text "-ARM" at 86.233,64.77 h3.05 r90
  text "Cavendish" at 83.274,56.769 h4.06 r90
  text "RST" at 115.062,49.422 h2.03
Bottom Overlay:
  lines w0.127: 93.019,63.144 94.34,64.465 ; 108.433,64.465 109.753,63.144
  text "Touch" at 118.743,82.7 h2.54
  text "BOOT" at 116.967,79.872 h1.52
  text "3V3" at 119.615,76.2 h2.03 r90
  text "MCU" at 112.268,74.572 h2.54
  text "LCD" at 100.965,51.204 h2.54
Top Solder:
  lines w0.254: 98.425,83.947 103.378,83.947 ; 100.711,86.487 101.092,86.106 ; 101.092,85.725 101.092,86.106 ; 101.473,86.487 101.092,86.106
  text "3.14" at 100.076,84.347 h2.03
  text "V" at 98.552,84.328 h2.29
Mechanical 15:
  lines w0.127: 78.359,49.022 81.983,49.022 ; 79.178,51.022 81.983,51.022 81.983,48.421 ; 79.204,56.522 84.483,56.522 84.483,48.308 ; 79.348,87.022 81.983,87.022 ; 79.983,47.625 79.983,51.022 ; 79.983,85.022 79.983,87.808 ; 99.983,51.022 99.983,52.739 99.983,76.361 ; 116.483,56.522 116.483,51.022 117.983,51.022 ; 117.983,49.022 120.618,49.022 ; 119.983,48.236 119.983,51.022
  text "5.5MM" at 79.647,52.426 h0.76 r90
  text "38MM" at 78.751,49.962 h1.52 r90
  text "2MM" at 79.654,49.302 h0.76 r90
  text "2MM" at 80.239,48.412 h0.76
  text "2.5MM" at 82.297,48.419 h0.76
  text "40MM" at 80.569,47.283 h1.52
